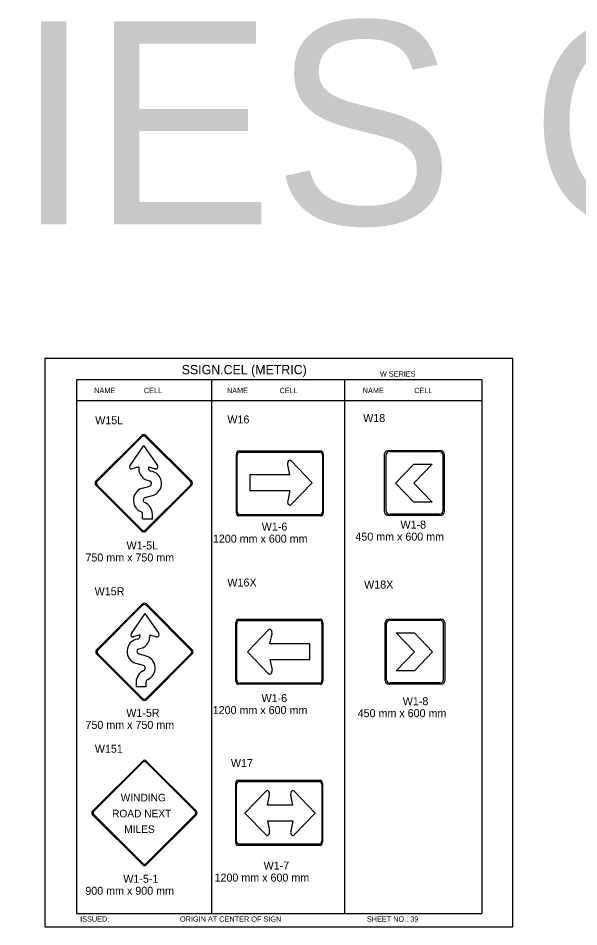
# Model space of a CAD drawing. Extents: x -12 to 6962, y -3756 to 679.
# Drawn here: x 1745.2 to 1955.2, y 225.3 to 565.9 of the extents above; entities that cross this region are included whole.
import ezdxf

# ---------------------------------------------------------------- set-up
doc = ezdxf.new("R2010")
doc.units = 0
for name, color, linetype in [('Level 1', 7, 'Continuous'), ('Level 2', 7, 'Continuous'), ('Level 3', 7, 'Continuous'), ('Level 62', 7, 'Continuous')]:
    doc.layers.add(name, color=color, linetype=linetype)

msp = doc.modelspace()

# ---------------------------------------------------------------- linework, layer by layer
at = {"layer": 'Level 1'}
for p, q in [((1918.81, 430.35), (1767.06, 430.35)), ((1767.06, 430.35), (1767.06, 230.35)), ((1817.64, 430.35), (1817.64, 230.35)), ((1867.47, 430.35), (1867.47, 230.35)), ((1918.81, 430.35), (1918.81, 230.35)), ((1817.64, 422.43), (1767.06, 422.43)), ((1868.23, 422.43), (1817.64, 422.43)), ((1918.81, 422.43), (1868.23, 422.43)), ((1774.3, 392.32), (1791.49, 409.52)), ((1774.8, 392.26), (1791.55, 409.02)), ((1792.92, 409.02), (1809.68, 392.26)), ((1792.99, 409.52), (1810.18, 392.32)), ((1792.18, 405.72), (1786.98, 398.21)), ((1792.18, 405.72), (1797.38, 398.21)), ((1826.95, 380.54), (1826.95, 402.5)), ((1827.26, 380.9), (1827.26, 402.14)), ((1827.77, 403.72), (1858.67, 403.72)), ((1828, 403.26), (1858.43, 403.26)), ((1859.18, 402.14), (1859.18, 380.9)), ((1859.48, 402.5), (1859.48, 380.54)), ((1882.44, 380.73), (1882.44, 402.68)), ((1883, 381.08), (1883, 402.33)), ((1883.93, 403.9), (1903.32, 403.9)), ((1884.37, 403.44), (1902.89, 403.44)), ((1904.25, 402.33), (1904.25, 381.08)), ((1904.81, 402.68), (1904.81, 380.73)), ((1846.92, 394.72), (1846.14, 398.55)), ((1855.33, 391.79), (1847.41, 400.02)), ((1886.56, 391.64), (1893.41, 398.74)), ((1893.41, 398.74), (1900.25, 398.74)), ((1900.25, 398.74), (1893.41, 391.64)), ((1790.33, 397.73), (1787.92, 396.99)), ((1790.33, 397.73), (1790.33, 397.14)), ((1794.03, 397.73), (1794.03, 397.12)), ((1794.03, 397.73), (1796.47, 396.99)), ((1846.92, 394.72), (1831.95, 394.72)), ((1831.95, 394.72), (1831.95, 388.86)), ((1855.33, 391.79), (1847.41, 383.59)), ((1791.49, 373.64), (1774.3, 390.83)), ((1791.55, 374.14), (1774.8, 390.89)), ((1791.7, 389.76), (1794.46, 390.55)), ((1792.34, 391.64), (1792.34, 391.64)), ((1809.68, 390.89), (1792.92, 374.14)), ((1810.18, 390.83), (1792.99, 373.64)), ((1831.95, 388.86), (1846.92, 388.86)), ((1842.9, 391.49), (1842.9, 391.49)), ((1846.92, 388.86), (1846.14, 385.03)), ((1893.41, 384.53), (1886.56, 391.64)), ((1893.41, 391.64), (1900.25, 384.53)), ((1893.58, 391.62), (1893.58, 391.62)), ((1792.74, 386.21), (1795.5, 387.02)), ((1900.25, 384.53), (1893.41, 384.53)), ((1791.75, 378.29), (1791.75, 380.04)), ((1791.75, 378.29), (1795.45, 378.29)), ((1795.45, 378.29), (1795.45, 380.04)), ((1858.67, 379.32), (1827.77, 379.32)), ((1858.43, 379.78), (1828, 379.78)), ((1903.32, 379.51), (1883.93, 379.51)), ((1902.89, 379.96), (1884.37, 379.96)), ((1774.54, 329.14), (1791.73, 346.33)), ((1775.04, 329.07), (1791.8, 345.83)), ((1793.17, 345.83), (1809.92, 329.07)), ((1793.23, 346.33), (1810.42, 329.14)), ((1792.67, 342.76), (1787.46, 335.25)), ((1792.67, 342.76), (1797.87, 335.25)), ((1884.12, 340.67), (1903.51, 340.67)), ((1826.76, 317.45), (1826.76, 339.4)), ((1827.07, 317.8), (1827.07, 339.05)), ((1827.58, 340.62), (1858.48, 340.62)), ((1827.82, 340.17), (1858.24, 340.17)), ((1858.99, 339.05), (1858.99, 317.8)), ((1859.29, 339.4), (1859.29, 317.45)), ((1882.62, 317.5), (1882.62, 339.45)), ((1883.18, 317.85), (1883.18, 339.1)), ((1884.55, 340.21), (1903.07, 340.21)), ((1904.44, 339.1), (1904.44, 317.85)), ((1905, 339.45), (1905, 317.5)), ((1790.81, 334.77), (1788.38, 334.03)), ((1790.81, 334.77), (1790.81, 334.16)), ((1794.49, 334.77), (1794.49, 334.18)), ((1794.49, 334.77), (1796.93, 334.03)), ((1831.08, 328.43), (1839, 336.62)), ((1839.49, 331.36), (1840.27, 335.19)), ((1893.6, 328.41), (1886.76, 335.51)), ((1886.76, 335.51), (1893.6, 335.51)), ((1893.6, 335.51), (1900.45, 328.41)), ((1854.46, 331.36), (1839.49, 331.36)), ((1854.46, 325.5), (1854.46, 331.36)), ((1791.73, 310.45), (1774.54, 327.64)), ((1791.8, 310.95), (1775.04, 327.7)), ((1793.15, 326.8), (1790.38, 327.59)), ((1792.58, 328.45), (1792.58, 328.45)), ((1809.92, 327.7), (1793.17, 310.95)), ((1810.42, 327.64), (1793.23, 310.45)), ((1831.08, 328.43), (1839, 320.2)), ((1842.93, 328.44), (1842.93, 328.44)), ((1886.76, 321.3), (1893.6, 328.41)), ((1893.53, 328.44), (1893.53, 328.44)), ((1900.45, 328.41), (1893.6, 321.3)), ((1792.08, 323.25), (1789.34, 324.06)), ((1839.49, 325.5), (1854.46, 325.5)), ((1839.49, 325.5), (1840.27, 321.67)), ((1893.6, 321.3), (1886.76, 321.3)), ((1789.39, 317.09), (1789.39, 315.33)), ((1793.07, 315.33), (1793.07, 317.08)), ((1793.07, 315.33), (1789.39, 315.33)), ((1858.48, 316.23), (1827.58, 316.23)), ((1858.24, 316.69), (1827.82, 316.69)), ((1903.51, 316.28), (1884.12, 316.28)), ((1903.07, 316.73), (1884.55, 316.73)), ((1773.04, 268.68), (1791.82, 287.46)), ((1773.48, 268.62), (1791.88, 287.01)), ((1793.11, 287.01), (1811.5, 268.62)), ((1793.16, 287.46), (1811.95, 268.68)), ((1827.47, 280.24), (1858.37, 280.24)), ((1827.71, 279.78), (1858.14, 279.78)), ((1826.66, 257.06), (1826.66, 279.02)), ((1826.97, 257.42), (1826.97, 278.66)), ((1830.11, 267.95), (1838.03, 276.18)), ((1856.46, 267.95), (1848.54, 276.18)), ((1858.88, 278.66), (1858.88, 257.42)), ((1859.19, 279.02), (1859.19, 257.06)), ((1838.52, 270.88), (1839.3, 274.72)), ((1848.05, 270.88), (1847.27, 274.72)), ((1848.05, 270.88), (1838.52, 270.88)), ((1791.82, 248.55), (1773.04, 267.33)), ((1791.88, 249), (1773.48, 267.39)), ((1792.35, 268.1), (1792.35, 268.1)), ((1811.5, 267.39), (1793.11, 249)), ((1811.95, 267.33), (1793.16, 248.55)), ((1830.11, 267.95), (1838.03, 259.76)), ((1842.93, 268.04), (1842.93, 268.04)), ((1856.46, 267.95), (1848.54, 259.76)), ((1838.52, 265.03), (1848.05, 265.03)), ((1838.52, 265.03), (1839.3, 261.19)), ((1848.05, 265.03), (1847.27, 261.19)), ((1858.37, 255.84), (1827.47, 255.84)), ((1858.14, 256.3), (1827.71, 256.3)), ((1767.06, 230.35), (1918.81, 230.35))]:
    msp.add_line(p, q, dxfattribs=at)
for centre, radius, start, end in [((1792.24, 408.77), 1.06, 45, 135), ((1792.24, 408.33), 0.969, 45, 135), ((1787.67, 397.78), 0.813, 148.0966, 286.7141), ((1795.02, 397.12), 4.68, 179.7888, 261.356), ((1795.02, 397.13), 0.988, 179.9136, 262.1046), ((1794.2, 391.51), 4.69, 286.2307, 81.5985), ((1796.69, 397.78), 0.813, 253.2859, 31.9034), ((1775.05, 391.58), 1.06, 135, 225), ((1775.48, 391.58), 0.969, 135, 225), ((1794.17, 391.51), 0.999, 286.4427, 81.9068), ((1809, 391.58), 0.969, 315, 45), ((1809.43, 391.58), 1.06, 315, 45), ((1793.01, 385.25), 4.69, 106.2083, 246.3971), ((1793.03, 385.25), 0.992, 106.4976, 246.5131), ((1790.77, 380.05), 4.68, 359.9985, 66.5015), ((1790.75, 380.03), 1.01, 1.2734, 67.7436), ((1792.24, 374.38), 1.06, 225, 315), ((1792.24, 374.82), 0.969, 225, 315), ((1792.48, 345.58), 1.06, 45, 135), ((1792.48, 345.14), 0.969, 45, 135), ((1788.15, 334.81), 0.813, 148.0966, 286.7141), ((1789.82, 334.16), 0.988, 277.8954, 0.0864), ((1789.82, 334.16), 4.68, 278.644, 0.2112), ((1797.17, 334.81), 0.813, 253.2859, 31.9034), ((1790.64, 328.55), 4.69, 98.4015, 253.7693), ((1775.29, 328.39), 1.06, 135, 225), ((1775.72, 328.39), 0.969, 135, 225), ((1790.67, 328.54), 0.999, 98.0932, 253.5573), ((1809.24, 328.39), 0.969, 315, 45), ((1809.67, 328.39), 1.06, 315, 45), ((1791.83, 322.29), 4.69, 293.6029, 73.7917), ((1794.07, 317.09), 4.68, 113.4985, 180.0015), ((1791.81, 322.29), 0.992, 293.4869, 73.5024), ((1794.09, 317.06), 1.01, 112.2564, 178.7266), ((1792.48, 311.2), 1.06, 225, 315), ((1792.48, 311.63), 0.969, 225, 315), ((1792.49, 286.79), 0.949, 45, 135), ((1792.49, 286.4), 0.87, 45, 135), ((1773.71, 268.01), 0.949, 135, 225), ((1774.1, 268.01), 0.87, 135, 225), ((1810.89, 268.01), 0.87, 315, 45), ((1811.28, 268.01), 0.949, 315, 45), ((1792.49, 249.61), 0.87, 225, 315), ((1792.49, 249.22), 0.949, 225, 315)]:
    msp.add_arc(centre, radius, start, end, dxfattribs=at)
for centre, major_axis, ratio, start_param, end_param in [((1827.77, 402.5), (0, 1.22), 0.666667, 0, 1.570796), ((1828, 402.14), (0, 1.12), 0.666667, 0, 1.570796), ((1858.43, 402.14), (0, 1.12), 0.666667, 4.712389, 6.283185), ((1858.67, 402.5), (0, 1.22), 0.666667, 4.712389, 6.283185), ((1883.93, 402.68), (-1.49, 0), 0.817773, 4.712389, 6.283185), ((1884.37, 402.33), (-1.37, 0), 0.817773, 4.712389, 6.283185), ((1902.89, 402.33), (1.37, 0), 0.817773, 0, 1.570796), ((1903.32, 402.68), (1.49, 0), 0.817773, 0, 1.570796), ((1846.96, 398.92), (0, 1.29), 0.666667, 5.725245, 8.139756), ((1846.96, 384.66), (0, -1.28), 0.666667, 4.41315, 6.847527), ((1827.77, 380.54), (0, -1.22), 0.666667, 4.712389, 6.283185), ((1828, 380.9), (0, -1.12), 0.666667, 4.712389, 6.283185), ((1858.43, 380.9), (0, -1.12), 0.666667, 0, 1.570796), ((1858.67, 380.54), (0, 1.22), 0.666667, 3.141593, 4.712389), ((1883.93, 380.73), (1.49, 0), 0.817773, 3.141593, 4.712389), ((1884.37, 381.08), (-1.37, 0), 0.817773, 0, 1.570796), ((1902.89, 381.08), (1.37, 0), 0.817773, 4.712389, 6.283185), ((1903.32, 380.73), (1.49, 0), 0.817773, 4.712389, 6.283185), ((1884.12, 339.45), (-1.49, 0), 0.817773, 4.712389, 6.283185), ((1903.51, 339.45), (1.49, 0), 0.817773, 0, 1.570796), ((1827.58, 339.4), (0, 1.22), 0.666667, 0, 1.570796), ((1827.82, 339.05), (0, 1.12), 0.666667, 0, 1.570796), ((1858.24, 339.05), (0, 1.12), 0.666667, 4.712389, 6.283185), ((1858.48, 339.4), (0, 1.22), 0.666667, 4.712389, 6.283185), ((1884.55, 339.1), (-1.37, 0), 0.817773, 4.712389, 6.283185), ((1903.07, 339.1), (1.37, 0), 0.817773, 0, 1.570796), ((1839.45, 335.56), (0, 1.28), 0.666667, 4.41315, 6.847527), ((1839.45, 321.3), (0, -1.29), 0.666667, 5.725245, 8.139756), ((1827.58, 317.45), (0, -1.22), 0.666667, 4.712389, 6.283185), ((1827.82, 317.8), (0, -1.12), 0.666667, 4.712389, 6.283185), ((1858.24, 317.8), (0, -1.12), 0.666667, 0, 1.570796), ((1858.48, 317.45), (0, 1.22), 0.666667, 3.141593, 4.712389), ((1884.12, 317.5), (1.49, 0), 0.817773, 3.141593, 4.712389), ((1884.55, 317.85), (-1.37, 0), 0.817773, 0, 1.570796), ((1903.07, 317.85), (1.37, 0), 0.817773, 4.712389, 6.283185), ((1903.51, 317.5), (1.49, 0), 0.817773, 4.712389, 6.283185), ((1827.47, 279.02), (0, 1.22), 0.666667, 0, 1.570796), ((1827.71, 278.66), (0, 1.12), 0.666667, 0, 1.570796), ((1858.14, 278.66), (0, 1.12), 0.666667, 4.712389, 6.283185), ((1858.37, 279.02), (0, 1.22), 0.666667, 4.712389, 6.283185), ((1838.48, 275.09), (0, -1.29), 0.666667, 1.285022, 3.699533), ((1848.09, 275.09), (0, 1.29), 0.666667, 5.725245, 8.139756), ((1838.48, 260.83), (0, 1.28), 0.666667, 2.577251, 5.011628), ((1848.09, 260.83), (0, -1.28), 0.666667, 4.41315, 6.847527), ((1827.47, 257.06), (0, -1.22), 0.666667, 4.712389, 6.283185), ((1827.71, 257.42), (0, -1.12), 0.666667, 4.712389, 6.283185), ((1858.14, 257.42), (0, -1.12), 0.666667, 0, 1.570796), ((1858.37, 257.06), (0, 1.22), 0.666667, 3.141593, 4.712389)]:
    msp.add_ellipse(centre, major_axis=major_axis, ratio=ratio, start_param=start_param, end_param=end_param, dxfattribs=at)
at = {"layer": 'Level 62'}
msp.add_lwpolyline([(1755.18, 225.31), (1930.44, 225.31), (1930.44, 438.4), (1755.18, 438.4)], close=True, dxfattribs=at)

# ---------------------------------------------------------------- texts
at = {"layer": 'Level 1'}
for s, p in [('WINDING', (1783.59, 272.33)), ('ROAD NEXT', (1780.35, 266.35)), ('   MILES', (1781.74, 260.49))]:
    msp.add_text(s, height=2.846, dxfattribs=at).set_placement(p)
at = {"layer": 'Level 2'}
for s, p in [('W15L', (1774.03, 413.7)), ('W16', (1823.54, 414.01)), ('W18', (1874.42, 414.56)), ('W16X', (1823.55, 352.88)), ('W18X', (1874.78, 352.12)), ('W15R', (1773.83, 349.59)), ('W151', (1773.9, 290.57)), ('W17', (1824.86, 285.22))]:
    msp.add_text(s, height=3, dxfattribs=at).set_placement(p)
at = {"layer": 'Level 3'}
for s, height, p in [('W-SERIES CELLS', 76.1938, (1404.77, 488.61)), ('SSIGN.CEL (METRIC)', 3.4642, (1806.44, 432.46)), ('W SERIES', 1.979, (1880.69, 431.59)), ('NAME', 1.98, (1773.67, 425.39)), ('CELL', 1.98, (1792.28, 425.39)), ('NAME', 1.98, (1823.4, 425.39)), ('CELL', 1.98, (1843.09, 425.39)), ('NAME', 1.98, (1874.27, 425.39)), ('CELL', 1.98, (1893.56, 425.39)), ('W1-6', 3, (1836.42, 373.81)), ('W1-8', 3, (1888.39, 374.58)), ('1200 mm x 600 mm', 3, (1818.12, 369.31)), ('450 mm x 600 mm', 3, (1871.51, 370.08)), ('W1-5L', 3, (1785.77, 366.76)), ('750 mm x 750 mm', 3, (1770.39, 362.26)), ('W1-6', 3, (1836.35, 309.54)), ('W1-8', 3, (1889.24, 308.39)), ('W1-5R', 3, (1785.68, 304.02)), ('1200 mm x 600 mm', 3, (1818.06, 305.04)), ('450 mm x 600 mm', 3, (1872.36, 303.89)), ('750 mm x 750 mm', 3, (1770.39, 299.52)), ('W1-7', 3, (1837.13, 246.76)), ('1200 mm x 600 mm', 3, (1818.75, 242.26)), ('W1-5-1', 3, (1784.56, 241.82)), ('900 mm x 900 mm', 3, (1770.34, 237.32)), ('ISSUED:', 1.98, (1768.4, 227.23)), ('ORIGIN AT CENTER OF SIGN', 1.9795, (1805.78, 227.23)), ('SHEET NO.: 39', 1.9795, (1875.81, 227.23))]:
    msp.add_text(s, height=height, dxfattribs=at).set_placement(p)

doc.saveas('drawing.dxf')
